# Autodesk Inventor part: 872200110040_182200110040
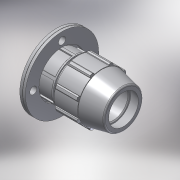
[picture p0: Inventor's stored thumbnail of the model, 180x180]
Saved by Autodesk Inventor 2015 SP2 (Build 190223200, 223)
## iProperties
Created: 2017-02
Part Number: 872200110040_182200110040
Material: PVC-Piping
Description: PLASSON COMPRESSION FLANGE ADAPTOR 110-4"
Document SubType Name: Modeling
Designer: KIM
Mass: 92.6774 g
Surface Area: 199.44 cm^2
Volume: 66.1981 cm^3
Density: 1.4 g/cm^3
Appearance: Smooth - White
Author: KIM
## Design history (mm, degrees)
derived "87220.ipt"
feature "Solid1::87220.ipt"
tag "TaggingFeature1"
body "Solid1"
other parameters: "d4" = 33.85714, "d5" = 75.84, "d7" = 181, "d9" = 33.85714, "d11" = 6.77143, "d12" = 144.8, "d13" = 120 deg, "d15" = 12 deg, "d18" = 5, "d19" = 35 deg, "d20" = 17.5 deg, "d21" = 168.33, "d23" = 0, "d25" = 360 deg, "d27" = 3.62, "d34" = 9.05, "d36" = 0, "d42" = 82.95, "d43" = 5.43, "d46" = 3, "d53" = 2, "d55" = 360 deg, "d70" = 237, "d73" = 19.75, "d74" = 90 deg, "d75" = 0.3, "d77" = 18, "d80" = 0, "d82" = 360 deg, "d85" = 153.85, "d86" = 144.8, "d87" = 2.44444, "d88" = 0.3, "d93" = 11.85, "d94" = 224, "E_" = 181, "H_" = 237, "l_" = 224, "S_" = 18
